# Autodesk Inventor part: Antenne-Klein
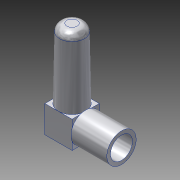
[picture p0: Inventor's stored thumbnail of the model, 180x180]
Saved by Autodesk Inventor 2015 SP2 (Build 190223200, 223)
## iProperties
Created: 2015-09
Part Number: Antenne-Klein
Material: Aluminium 6061
Document SubType Name: Modeling
Designer: rYan
Density: 2.7 g/cm^3
Appearance: Aluminium - flach
Mass: 3.64939 g
Surface Area: 11.5991 cm^2
Volume: 1.35163 cm^3
Author: rYan
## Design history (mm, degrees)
sketch "Skizze1"
  geometry: L1 (-3.7, 3.7)-(3.7, 3.7); L2 (3.7, 3.7)-(3.7, -3.7); L3 (3.7, -3.7)-(-3.7, -3.7); L4 (-3.7, -3.7)-(-3.7, 3.7); L5 (0, 5.18)-(0, -5.18) reference; L6 (-5.18, 0)-(5.18, 0) reference; 1 further point
  constraints: 8 end point, 2 parallel, 1 horizontal, 1 perpendicular, 2 other
  dimensions: "d0" = 7.4 distance of L1.start L1.end; "d1" = 7.4 distance of L1.end L2.end
extrude "Extrusion1" new body sketch "Skizze1" distance "d2" = 7.4; taper "d3" = 0 deg
sketch "Skizze2"
  geometry: C1 r 3.7 at (0, 0); 1 further point
  constraints: 1 centre point, 1 coincident
  dimensions: "d4" = 7.4 diameter of C1
extrude "Extrusion2" join sketch "Skizze2" distance "d5" = 19; taper "d6" = -1 deg
fillet "Rundung1" dims "d7" = 2
sketch "Skizze3"
  geometry: L1 (-7.4, 7.4)-(-7.4, 3.7) reference; L2 (-7.4, 3.7)-(-7.4, 0) reference; L3 (-7.4, 0)-(0, 0) reference; L4 (0, 7.4)-(0, 0) reference; L5 (-7.4, 7.4)-(0, 7.4) reference; L6 (-7.4, 3.7)-(0, 3.7); L7 (0, 7.4)-(0, 0) reference; L8 (-7.4, 0)-(0, 0) reference; L9 (-3.7, 0)-(-3.7, 7.4); L10 (-7.4, 7.4)-(0, 7.4) reference; C1 r 4 at (-3.7, 3.7); C2 r 3 at (-3.7, 3.7)
  constraints: 4 end point, 4 midpoint, 2 centre point, 1 coincident
  dimensions: "d8" = 8 diameter of C1; "d9" = 6 diameter of C2
extrude "Extrusion3" join sketch "Skizze3" distance "d10" = 9.8; taper "d11" = 0 deg
node "Volumenkörper1"
node "Projizierte Kontur1"
